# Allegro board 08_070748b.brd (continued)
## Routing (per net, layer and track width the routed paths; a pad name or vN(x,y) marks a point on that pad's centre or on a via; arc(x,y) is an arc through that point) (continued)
VOSNS0+: length 123.2
  LAYER_3 w0.254: TP16.1 v1(143.51,97.92)
  LAYER_4 w0.152: 95.76,82.8 95.73,82.77 91.78,82.77 v2(91.26,82.26)
  LAYER_4 w0.254: TP16.1 134.24,112.4 125.83,103.99 v1(123.19,101.35) 123.19,100.19 107.96,84.96 97.46,84.96 96.39,83.89 96.39,83.44 95.76,82.8
  LAYER_5 w0.254: v1(152.15,87.63) 152.15,87.63 152.15,92.07 150.62,93.6 130.94,93.6 v1(123.19,101.35)
  BOTTOM w0.254: R79.1 v1(143.51,97.92) ; R121.2 v1(152.15,87.63)
  BOTTOM w0.381: R61.2 TP16.1
VOSNS0-: length 196
  LAYER_4 w0.152: v2(91.26,83.26) 91.39,83.38 91.58,83.38 91.93,83.74 95.59,83.74 95.76,83.91
  LAYER_4 w0.203: v1(122.49,101.46) 122.47,101.46 122.47,101.46 ; 95.8,83.95 95.76,83.91
  LAYER_4 w0.254: v1(197.1,105.41) 197.1,105.54 197.49,105.92 TP17.1 183.77,113.92 168.91,113.92 164.59,109.6 154.81,109.6 149.35,115.06 142.37,115.06 140.21,112.9 133.91,112.9 122.47,101.46 ; v1(122.49,101.46) 122.49,100.14 107.82,85.47 97.32,85.47 95.8,83.95
  LAYER_5 w0.254: v1(152.15,86.11) 151.51,86.74 151.51,91.95 150.37,93.09 130.68,93.09 123.01,100.76 122.95,100.76 122.49,101.22 v1(122.49,101.46)
  BOTTOM w0.254: R80.1 v1(197.1,105.41) ; R122.2 v1(152.15,86.11)
  BOTTOM w0.381: R62.1 TP17.1
VOSNS1+: length 78.2
  LAYER_3 w0.254: v1(141.99,79.76) 143.51,81.28 TP18.1
  LAYER_4 w0.381: v1(143.51,94.74) TP18.1
  LAYER_5 w0.152: 95.54,84.74 89.06,84.74 89.04,84.71 88.72,84.71 v2(88.27,84.26)
  LAYER_5 w0.254: 95.54,84.74 95.91,84.74 98.81,87.63 TP18.1
  BOTTOM w0.254: R63.2 TP18.1 ; v1(141.99,79.76) 142.45,80.22 R96.1 ; R79.2 v1(143.51,94.74)
VOSNS1-: length 131.3
  LAYER_4 w0.152: v2(88.27,85.26) 87.78,84.77 87.78,83.06 88.54,82.29 88.54,82.22 88.83,81.94 88.9,81.94 89.06,81.77 95.76,81.77
  LAYER_4 w0.203: v1(197.1,102.11) 192.33,97.33
  LAYER_4 w0.254: 192.33,97.33 183.51,88.52 TP19.1 182.5,82.17 110.62,82.17 109.21,80.76 96.77,80.76 95.76,81.77
  BOTTOM w0.254: R64.1 TP19.1 R97.1 ; R80.2 v1(197.1,102.11)
VOSNS2+: length 76.3
  LAYER_3 w0.254: TP12.1 143.51,72.52 143.38,72.64 143.38,77.6 v1(141.99,78.99)
  LAYER_4 w0.254: TP12.1 v1(143.51,67.82)
  LAYER_5 w0.152: v2(88.27,77.26) 88.78,76.74 95.47,76.74 95.5,76.71 95.76,76.71
  LAYER_5 w0.254: 95.76,76.71 96.52,75.95 96.52,74.68 99.31,71.88 TP12.1
  BOTTOM w0.254: R96.2 142.45,78.53 v1(141.99,78.99) ; R17.2 146.2,71.09 145.41,71.88 TP12.1 ; v1(143.51,67.82) R108.1
VOSNS2-: length 130.4
  LAYER_4 w0.152: 95.76,76.87 95.63,76.74 89.06,76.74 89.03,76.71 88.72,76.71 v2(88.27,76.26)
  LAYER_4 w0.254: v1(197.1,57.53) 197.1,58.17 183.51,71.75 TP14.1 180.97,73.03 176.02,73.03 174.24,74.8 112.9,74.8 108.59,79.12 98.01,79.12 95.76,76.87
  BOTTOM w0.254: R20.1 TP14.1 R97.2 ; v1(197.1,57.53) R109.1
VOSNS3+: length 87.1
  LAYER_3 w0.254: v1(143.51,64.77) TP13.1
  LAYER_4 w0.152: 95.76,75.74 91.78,75.74 v2(91.26,76.26)
  LAYER_4 w0.203: 95.76,75.74 95.8,75.74
  LAYER_4 w0.254: TP13.1 133.6,46.99 106.54,74.06 97.49,74.06 95.8,75.74
  BOTTOM w0.254: R108.2 v1(143.51,64.77) ; R8.2 TP13.1
VOSNS3-: length 156.5
  LAYER_4 w0.152: v2(91.26,75.26) 91.45,75.26 91.61,75.09 91.62,75.09 91.94,74.77 95.76,74.77
  LAYER_4 w0.254: 95.76,74.77 95.91,74.77 97.09,73.6 106.23,73.6 133.35,46.48 140.21,46.48 143,43.69 144.91,43.69 150.5,38.1 163.45,38.1 170.94,45.59 182.37,45.59 TP15.1
  LAYER_6 w0.254: TP15.1 196.34,31.88 196.6,31.88 198.5,33.78 198.5,52.83 v1(197.1,54.23)
  BOTTOM w0.254: R109.2 v1(197.1,54.23) ; R9.1 TP15.1
VOUT0: length 152.2
  LAYER_4 w0.254: J3.1 127.51,147.17 107.95,127.61 107.95,91.44 107.57,91.06 v1(106.93,91.06)
  LAYER_5 w0.254: v1(150.24,112.4) 148.34,112.4 139.57,103.63 120.41,103.63 110.58,93.8 104.7,93.8 104.44,93.55 104.44,91.58 104.96,91.06 v1(105.03,91.06)
  BOTTOM w0.305: v1(105.03,91.06) 105.03,90.17 105.16,90.04 106.68,90.04 106.93,90.3 v1(106.93,91.06)
  BOTTOM w0.381: R61.1 v1(150.24,112.4)
  BOTTOM w0.508: J3.1 C71.1
  BOTTOM w1.27: 120.78,152.02 118.76,152.02 C84.2 C79.1 120.77,152.01 120.78,152.02 ; 120.78,152.02 J3.1 127.52,152.01 C75.1
  vias: v1(97.41,91.06) v1(98.42,91.06) v1(99.31,91.06) v1(101.22,91.06) v1(102.23,91.06) v1(103.12,91.06) v1(106.05,91.06) v1(121.92,116.59) v1(121.92,114.68) v1(123.83,116.59) v1(123.83,114.68) v1(125.73,116.59) v1(125.73,114.68) v1(127.63,116.59) v1(127.63,114.68) v1(128.52,118.75) v1(129.54,118.75) v1(129.54,116.59) v1(129.54,114.68) v1(130.43,118.75) v1(131.44,116.59) v1(131.44,114.68) v1(134.24,118.62) v1(135.25,118.62) v1(136.14,118.62) v1(139.32,118.62) v1(140.34,118.62) v1(140.97,107.19) v1(141.22,118.62) v1(141.61,107.19) v1(144.53,118.62) v1(144.53,106.3) v1(144.53,105.66) v1(145.54,118.62) v1(146.43,118.62) v1(146.69,107.19) v1(147.7,107.19) v1(148.72,107.19) v1(149.48,118.62) v1(150.5,118.62) v1(151.38,118.62) v1(151.76,107.19) v1(152.78,107.19) v1(153.67,107.19) v1(153.92,119) v1(154.94,119) v1(155.83,119) v1(156.72,107.19) v1(157.73,107.19) v1(158.75,107.19) v1(161.67,107.19) v1(162.69,107.19) v1(163.7,107.19) v1(166.37,122.17) v1(166.37,121.41) v1(166.37,120.52) v1(166.37,119.76) v2(93.26,90.26) v2(93.26,89.26) v2(93.26,88.26) v2(93.26,87.26) v2(93.26,86.26) v2(94.26,90.26) v2(94.26,89.26) v2(94.26,88.26) v2(94.26,87.26) v2(94.26,86.26) v2(95.26,90.26) v2(95.26,89.26) v2(95.26,88.26) v2(95.26,87.26) v2(95.26,86.26)
VOUT0_CFG: length 94.7
  LAYER_4 w0.152: 88.23,90.77 88.23,90.29
  LAYER_4 w0.203: 88.23,90.77 88.65,91.19 88.65,92.63 88.06,93.21 88.06,111.33 81.92,117.48 v1(81.92,118.24) ; 88.23,90.29 v2(88.27,90.26)
  LAYER_5 w0.203: v2(88.27,90.26) 88.27,90.81 87.89,91.19 v1(79.25,91.19)
  LAYER_6 w0.203: v1(79.25,91.19) 79.25,87.44 79.35,87.34 79.35,70.36 79.25,70.25 79.25,46.35 v1(84.07,41.53)
  BOTTOM w0.203: R55.1 v1(81.92,118.24) R46.2 ; R54.1 v1(84.07,41.53)
VOUT1: length 182.5
  TOP w0.381: CO12.2 98.42,83.69
  LAYER_5 w0.254: J4.1 194.44,89.66 191.52,86.74 191.52,85.72 186.31,80.52 181.17,80.52 180.59,81.09 110.11,81.09 108.38,82.81 107.07,82.81 v1(107.06,82.8) ; v1(155.45,87.63) 157.35,85.72 168.15,85.72 v1(169.04,86.61)
  LAYER_6 w0.254: v1(150.37,87.63) 147.45,84.71 109.35,84.71 108.59,83.95 106.93,83.95 106.17,83.19 v1(106.17,82.8)
  BOTTOM w0.203: CO37.2 168.91,86.49 v1(169.04,86.61)
  BOTTOM w0.254: v1(155.45,87.63) R121.1 ; R63.1 v1(150.37,87.63) ; v1(106.17,82.8) CO10.2 106.81,83.82 107.06,83.57 v1(107.06,82.8)
  BOTTOM w0.508: J4.1 C72.1
  BOTTOM w1.27: C80.1 J4.1 C76.1 C85.2
  vias: v1(97.54,83.06) v1(98.42,83.06) v1(99.31,83.06) v1(101.35,83.06) v1(102.23,83.06) v1(103.12,83.06) v1(105.28,83.06) v1(113.41,88.9) v1(114.3,88.9) v1(115.19,88.9) v1(118.49,88.9) v1(119.38,88.9) v1(120.27,88.9) v1(123.57,88.9) v1(124.46,88.9) v1(125.35,88.9) v1(128.27,101.35) v1(128.27,99.44) v1(128.65,88.9) v1(129.54,88.9) v1(130.18,101.35) v1(130.18,99.44) v1(130.43,88.9) v1(132.08,101.35) v1(132.08,99.44) v1(133.99,101.35) v1(133.99,99.44) v1(134.37,88.9) v1(135.25,88.9) v1(135.89,101.35) v1(135.89,99.44) v1(136.14,88.9) v1(137.8,101.35) v1(137.8,99.44) v1(141.1,99.57) v1(141.86,99.57) v1(144.53,100.46) v1(144.53,99.69) v1(146.05,83.19) v1(146.69,99.69) v1(146.94,83.19) v1(147.7,99.69) v1(147.83,83.19) v1(148.72,99.69) v1(151.13,83.19) v1(151.76,99.69) v1(152.02,83.19) v1(152.78,99.69) v1(152.91,83.19) v1(153.8,99.69) v1(155.83,83.19) v1(156.46,99.69) v1(156.84,83.19) v1(157.48,99.69) v1(157.86,83.19) v1(158.5,99.69) v1(161.04,83.19) v1(161.42,99.69) v1(161.93,83.19) v1(162.56,99.69) v1(162.81,83.19) v1(163.58,99.69) v1(165.99,83.19) v1(166.88,83.19) v1(167.77,83.19) v2(93.26,85.26) v2(93.26,84.26) v2(93.26,83.26) v2(93.26,82.26) v2(93.26,81.26) v2(94.26,85.26) v2(94.26,84.26) v2(94.26,83.26) v2(94.26,82.26) v2(94.26,81.26) v2(95.26,85.26) v2(95.26,84.26) v2(95.26,83.26) v2(95.26,82.26) v2(95.26,81.26)
VOUT1_CFG: length 102.1
  LAYER_4 w0.152: 87.75,90.81 87.75,89.77 v2(88.27,89.26)
  LAYER_4 w0.203: 87.75,90.81 87.75,91.95 87.5,92.2 87.5,92.66 87.66,92.82 87.66,110.85 v1(80.01,118.49)
  LAYER_5 w0.152: v2(88.27,89.26) 87.76,89.76 87.76,90.45 87.44,90.76
  LAYER_5 w0.203: 87.44,90.76 79.97,90.76 79.83,90.63 79.02,90.63 78.9,90.74 v1(78.17,90.74)
  LAYER_6 w0.203: v1(78.17,90.74) 78.17,87.95 78.94,87.17 78.94,70.52 78.49,70.07 78.49,46.23 83.19,41.53 v1(83.19,38.99)
  BOTTOM w0.203: R131.1 R54.2 v1(83.19,38.99) ; R47.2 v1(80.01,118.49) R56.1
VOUT2: length 165
  LAYER_5 w0.254: v1(107.06,76.2) 107.95,76.2 109.6,77.85 185.42,77.85 193.42,69.85 J5.1
  LAYER_6 w0.254: v1(106.17,76.2) 107.19,75.18 148.97,75.18 150.22,73.94 v1(150.22,71.09)
  BOTTOM w0.203: 203.67,69.85 C77.1 ; 188.69,69.86 C81.1
  BOTTOM w0.254: R17.1 v1(150.22,71.09)
  BOTTOM w0.381: v1(107.06,76.2) 107.06,75.82 106.43,75.18 CO20.2 v1(106.17,76.2)
  BOTTOM w0.508: C73.1 J5.1
  BOTTOM w1.27: 203.67,69.85 J5.1 188.72,69.85 188.71,69.86 C86.2
  vias: v1(97.54,76.2) v1(98.42,76.2) v1(99.31,76.2) v1(101.35,76.2) v1(102.23,76.2) v1(103.12,76.2) v1(105.28,76.2) v1(113.41,73.03) v1(114.3,73.03) v1(115.19,73.03) v1(118.49,73.03) v1(119.38,73.03) v1(120.27,73.03) v1(123.57,73.03) v1(124.46,73.03) v1(125.35,73.03) v1(128.27,69.6) v1(128.27,67.69) v1(128.65,73.03) v1(129.54,73.03) v1(130.18,69.6) v1(130.18,67.69) v1(130.43,73.03) v1(132.08,69.6) v1(132.08,67.69) v1(133.99,69.6) v1(133.99,67.69) v1(134.37,73.03) v1(135.25,73.03) v1(135.89,69.6) v1(135.89,67.69) v1(136.14,73.03) v1(137.8,69.6) v1(137.8,67.69) v1(141.1,59.94) v1(141.1,59.31) v1(141.1,58.67) v1(141.73,58.67) v1(146.05,76.71) v1(146.81,59.94) v1(146.94,76.71) v1(147.7,59.94) v1(147.83,76.71) v1(148.59,59.94) v1(151,76.71) v1(151.89,76.71) v1(151.89,59.94) v1(152.78,76.71) v1(152.78,59.94) v1(153.67,59.94) v1(156.08,76.71) v1(156.59,59.94) v1(156.97,76.71) v1(157.48,59.94) v1(157.86,76.71) v1(158.37,59.94) v1(160.91,76.71) v1(161.8,76.71) v1(161.8,59.94) v1(162.69,76.71) v1(162.69,59.94) v1(163.58,59.94) v1(165.99,76.71) v1(166.88,76.71) v1(167.77,76.71) v2(93.26,78.26) v2(93.26,77.26) v2(93.26,76.26) v2(93.26,75.26) v2(93.26,74.26) v2(94.26,78.26) v2(94.26,77.26) v2(94.26,76.26) v2(94.26,75.26) v2(94.26,74.26) v2(95.26,78.26) v2(95.26,77.26) v2(95.26,76.26) v2(95.26,75.26) v2(95.26,74.26)
VOUT2_CFG: length 34.6
  LAYER_4 w0.152: 87.63,68.71 87.78,68.86 87.78,69.46 88,69.67 88,69.71 88.27,69.97 v2(88.27,70.26)
  LAYER_4 w0.203: 87.63,68.71 87.22,68.3 87.22,62.25 87.25,62.22 87.25,43.05 v1(88.9,41.4)
  BOTTOM w0.203: R23.1 v1(88.9,41.4) R11.2 R140.1 R131.2
VOUT3: length 149.5
  TOP w0.381: CO28.2 v1(98.42,68.33)
  LAYER_4 w0.254: v1(106.97,68.36) 107.52,67.81 107.52,67.32 106.55,66.36 106.55,31.75 127.51,10.8 J6.1
  LAYER_5 w0.254: v1(150.11,46.99) 130.81,66.29 110.24,66.29 107.44,69.09 106.68,69.09 106.05,68.45 v1(106.05,68.33)
  BOTTOM w0.203: v1(106.97,68.36) 106.97,68.42 CO29.2 ; 129.54,39.5 v1(129.54,40.77) ; 106.05,69.28 v1(106.05,68.33)
  BOTTOM w0.254: R8.1 v1(150.11,46.99)
  BOTTOM w0.508: C74.1 J6.1
  BOTTOM w1.27: C78.1 134.71,7.49 J6.1 127.47,7.53 C82.1 C87.2
  vias: v1(97.54,68.33) v1(99.31,68.33) v1(101.35,68.33) v1(102.23,68.33) v1(103.12,68.33) v1(105.16,68.33) v1(121.92,46.1) v1(121.92,44.2) v1(123.83,46.1) v1(123.83,44.2) v1(125.73,46.1) v1(125.73,44.2) v1(127.63,46.1) v1(127.63,44.2) v1(128.65,40.77) v1(129.54,46.1) v1(129.54,44.2) v1(130.43,40.77) v1(131.44,46.1) v1(131.44,44.2) v1(134.37,40.77) v1(135.25,40.77) v1(136.14,40.77) v1(139.45,40.77) v1(140.34,40.77) v1(141.1,53.72) v1(141.1,53.09) v1(141.1,52.32) v1(141.22,40.77) v1(141.86,52.32) v1(144.53,40.77) v1(145.41,40.77) v1(146.3,40.77) v1(146.81,52.45) v1(147.7,52.45) v1(148.59,52.45) v1(149.48,40.77) v1(150.37,40.77) v1(151.26,40.77) v1(151.89,52.45) v1(152.78,52.45) v1(153.67,52.45) v1(154.05,40.51) v1(154.94,40.51) v1(155.83,40.51) v1(156.84,52.45) v1(157.73,52.45) v1(158.62,52.45) v1(161.54,52.45) v1(162.43,52.45) v1(163.32,52.45) v1(166.37,39.24) v1(166.37,38.61) v1(166.37,37.97) v1(166.37,37.34) v2(93.26,73.26) v2(93.26,72.26) v2(93.26,71.26) v2(93.26,70.26) v2(93.26,69.26) v2(94.26,73.26) v2(94.26,72.26) v2(94.26,71.26) v2(94.26,70.26) v2(94.26,69.26) v2(95.26,73.26) v2(95.26,72.26) v2(95.26,71.26) v2(95.26,70.26) v2(95.26,69.26)
VOUT3_CFG: length 60.8
  LAYER_4 w0.152: 88.21,68.71 88.27,68.76 v2(88.27,69.26)
  LAYER_4 w0.203: 88.21,68.71 87.63,68.13 87.63,62.42 88.27,61.78 88.27,46.1 90.81,43.56 v1(90.81,41.4)
  LAYER_6 w0.203: v2(88.27,69.26) 86.36,67.35 86.36,46.48 85.6,45.72 85.6,41.66 v1(85.72,41.53)
  BOTTOM w0.203: v1(85.72,41.53) 85.64,41.44 R140.2 ; R24.1 v1(90.81,41.4) R12.2
VTRIM0_CFG: length 34.8
  LAYER_6 w0.152: v2(89.26,87.26) 89.08,87.26 88.56,87.77 88.06,87.77 87.78,88.06 87.78,90.65 87.63,90.81
  LAYER_6 w0.203: v1(87.63,118.24) 87.63,118.02 87.79,117.86 87.79,93.01 87.82,92.98 87.83,92.99 88.29,92.99 88.62,92.66 88.62,92.2 88.29,91.87 87.93,91.87 87.63,91.57 87.63,90.81
  BOTTOM w0.203: R57.1 v1(87.63,118.24) R48.2
VTRIM1_CFG: length 42.9
  LAYER_4 w0.152: v2(89.26,88.26) 88.78,88.74 88.78,90.59 89,90.81
  LAYER_4 w0.203: v1(83.82,118.24) 83.82,116.45 88.47,111.8 88.47,93.38 89.05,92.8 89.05,90.86 89,90.81
  LAYER_5 w0.203: v1(83.82,118.24) 82.93,119.13 78.99,119.13 v1(78.11,118.24)
  BOTTOM w0.203: R125.2 R137.1 v1(78.11,118.24) ; R49.2 v1(83.82,118.24) R58.1
VTRIM2_CFG: length 97.1
  LAYER_4 w0.152: v2(90.26,69.26) 90.26,68.71
  LAYER_4 w0.203: 90.26,68.71 90.26,63.09 90.42,62.93 90.42,61.46 90.26,61.3 90.26,49.44 96.4,43.31 98.04,43.31 98.98,42.37 98.98,41.04 98.66,40.72 97.08,40.72 v1(96.52,41.27)
  LAYER_5 w0.152: 80.77,69.77 89.75,69.77 v2(90.26,69.26)
  LAYER_5 w0.203: 80.77,69.77 79.32,69.77 v1(78.36,70.73)
  LAYER_6 w0.203: v1(78.36,70.73) 78.36,79.35 78.54,79.52 78.54,79.99 78.51,80.01 78.51,82.25 77.22,83.54 v1(77.22,115.74)
  BOTTOM w0.203: R25.1 v1(96.52,41.27) R13.2 ; R145.1 v1(77.22,115.74) R137.2
VTRIM3_CFG: length 93.5
  LAYER_4 w0.152: v2(89.26,69.26) 89.26,68.71
  LAYER_4 w0.203: 89.26,68.71 89.26,62.94 89.61,62.59 89.61,61.79 89.26,61.45 89.26,49.29 94.62,43.94 v1(94.61,41.4)
  LAYER_5 w0.203: v2(89.26,69.26) 88.28,68.28 v1(76.07,68.28)
  LAYER_6 w0.203: v1(74.72,115.74) 74.72,83.45 75.97,82.19 75.97,79.91 75.95,79.89 75.95,79.53 75.97,79.5 75.97,68.38 v1(76.07,68.28)
  BOTTOM w0.203: R14.2 v1(94.61,41.4) R26.1

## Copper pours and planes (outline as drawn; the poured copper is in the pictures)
AGND on LAYER_2: 89.92,85.6 89.92,84.84 91.57,84.84 91.57,85.6
AGND on LAYER_2: 89.92,74.68 89.92,73.91 91.57,73.91 91.57,74.68
GND_POWER on TOP: 1.27,158.75 237.49,158.75 237.49,1.27 1.27,1.27
GND_POWER on BOTTOM: 117.35,6.48 117.35,2.79 125.73,2.79 125.73,6.48
GND_POWER on BOTTOM: 117.98,156.59 117.98,153.03 126.11,153.03 126.11,156.59
GND_POWER on BOTTOM: 129.16,156.59 129.16,153.03 135.25,153.03 135.25,156.59
GND_POWER on BOTTOM: 129.16,6.48 129.16,2.79 135.38,2.79 135.38,6.48
GND_POWER on BOTTOM: 186.06,70.61 186.06,64.9 194.94,64.9 194.94,70.61
GND_POWER on BOTTOM: 197.87,68.96 197.87,64.9 204.34,64.9 204.34,68.96
GND_POWER on BOTTOM: 197.99,88.77 197.99,85.09 204.47,85.09 204.47,88.77
GND_POWER on BOTTOM: 1.27,158.75 1.27,1.27 237.49,1.27 237.49,158.75 ; 16 cut-outs
GND_POWER on BOTTOM: 185.93,88.77 185.93,85.09 194.69,85.09 194.69,88.77
GND_POWER on LAYER_2, LAYER_3, LAYER_7: 1.27,158.75 1.27,1.27 237.49,1.27 237.49,158.75
GND_POWER on LAYER_4: 1.27,158.75 237.49,158.75 237.49,1.27 1.27,1.27 ; 15 cut-outs
GND_POWER on LAYER_5: 1.27,158.75 237.49,158.75 237.49,1.27 1.27,1.27 ; 11 cut-outs
GND_POWER on LAYER_6: 1.27,158.75 237.49,158.75 237.49,1.27 1.27,1.27 ; 2 cut-outs
VIN on BOTTOM (solid shape): 41.15,101.6 39.24,101.6 39.24,105.79 41.15,105.79
VIN on BOTTOM (solid shape): 41.15,53.34 39.24,53.34 39.24,57.53 41.15,57.53
VIN on TOP: 1.27,109.98 8.89,109.98 8.89,108.33 64.52,108.33 64.52,51.31 22.1,51.31 22.1,80.77 1.27,80.77 ; 2 cut-outs
VIN on BOTTOM: 8.89,109.98 8.89,108.33 64.52,108.33 64.52,51.31 22.1,51.31 22.1,80.77 1.27,80.77 1.27,109.98 ; 2 cut-outs
VIN01 on TOP, BOTTOM: 64.77,108.33 86.61,108.33 86.61,81.03 84.84,81.03 84.84,98.81 64.77,98.81
VIN23 on TOP, BOTTOM: 64.77,60.71 84.84,60.71 84.84,78.49 86.61,78.49 86.61,51.31 64.77,51.31
Net_2 on LAYER_2 (solid shape): 92.71,84.84 91.19,84.84 91.19,85.6 92.71,85.6
Net_2 on LAYER_2 (solid shape): 92.71,73.91 91.19,73.91 91.19,74.68 92.71,74.68
UNNAMED_2_ADLTM4683_I1_SW01 on TOP: 80.9,86.26 78.49,86.26 78.49,88.39 80.9,88.39 80.9,88.65 82.57,88.65 82.57,85.85 80.9,85.85
UNNAMED_2_ADLTM4683_I1_SW11 on TOP: 80.87,82.2 78.49,82.2 78.49,84.33 80.9,84.33 80.9,84.71 82.57,84.71 82.57,81.79 80.87,81.79
UNNAMED_2_ADLTM4683_I1_SW21 on TOP: 80.87,75.08 78.49,75.08 78.49,77.22 80.9,77.22 80.9,77.6 82.57,77.6 82.57,74.93 80.87,74.93
UNNAMED_2_ADLTM4683_I1_SW31 on TOP: 80.87,71.27 78.49,71.27 78.49,73.41 80.9,73.41 80.9,73.66 82.57,73.66 82.57,70.87 80.87,70.87
UNNAMED_4_CAP_I295_N2 on BOTTOM: 157.86,131.57 176.4,131.57 176.4,98.81 169.16,98.81 169.16,123.83 157.86,123.83
UNNAMED_4_CAP_I345_N2 on BOTTOM: 176.4,60.71 176.4,27.69 157.86,27.69 157.86,35.69 169.16,35.69 169.16,60.71
UNNAMED_4_CNBNC5P_I301_CNTR on BOTTOM: 162.56,146.69 173.23,146.69 173.23,132.84 169.67,132.84 169.67,136.91 164.97,136.91 164.97,132.84 162.56,132.84
UNNAMED_4_CNBNC5P_I354_CNTR on BOTTOM: 157.86,26.8 161.16,26.8 161.16,22.99 164.72,22.99 164.72,26.54 168.53,26.54 168.53,13.21 157.86,13.21
VOUT0 on TOP: 124.82,123.57 168.91,123.57 168.91,103.38 126.2,103.38 108.77,85.85 92.96,85.85 92.96,91.31 107.31,91.31 107.7,91.69 107.7,98.04 116.05,110.49 119.17,115.09
VOUT0 on BOTTOM: 168.91,103.38 126.2,103.38 108.77,85.85 92.96,85.85 92.96,91.31 103.39,91.31 103.4,91.32 107.31,91.31 107.7,91.69 107.7,98.04 124.82,123.57 168.91,123.57 ; 1 cut-out
VOUT1 on TOP: 126.44,103.12 168.91,103.12 168.91,81.79 144.91,81.79 144.91,82.68 96.01,82.68 96.01,80.9 92.96,80.9 92.96,85.6 108.82,85.6
VOUT1 on BOTTOM: 126.44,103.12 168.91,103.12 168.91,81.79 144.91,81.79 144.91,82.68 96.01,82.68 96.01,80.9 92.96,80.9 92.96,85.6 108.82,85.6 ; 2 cut-outs
VOUT2 on TOP: 92.96,78.61 96.01,78.61 96.01,76.71 144.91,76.71 144.91,77.72 168.91,77.72 168.91,56.39 127.66,56.39 110.04,73.91 92.96,73.91
VOUT2 on BOTTOM: 96.01,76.71 144.91,76.71 144.91,77.72 168.91,77.72 168.91,56.39 127.66,56.39 110.29,73.66 92.96,73.66 92.96,78.61 96.01,78.61 ; 1 cut-out
VOUT3 on TOP: 92.96,73.66 109.95,73.66 127.38,56.13 168.91,56.13 168.91,35.92 125.32,35.92 107.7,61.75 107.69,68.07 92.96,68.07
VOUT3 on BOTTOM: 92.96,73.66 109.95,73.66 127.38,56.13 168.91,56.13 168.91,35.94 125.31,35.92 107.7,61.72 107.7,68.07 92.96,68.07 ; 2 cut-outs

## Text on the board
Ref Des/Silkscreen Bottom: 08-070748B | TSNS0 | TSNS1 | TSNS2 | TSNS3 | 2 | 1
User.Comments: 4 | A1Z | A2Z | VARIANTS | 4 PHASE 4 OUTPUT | 4 PHASE 1 OUTPUT | CIRCUIT CONFIGUATION | 125A | 31.25A PER CHANNEL | MAX OUTPUT CURRENT | PLEASE SEE BILL OF MATERILL TO MARK EACH VERSION CORRECTLY | WITH BLACK PERMANENT MARKER INSIDE SILKSCREEN BLOCK PROVIDE | 4.    THERE ARE 2 ASSEMBLY VARIANTS 01-070748B-01, 01-070748B-02. | *ASSEMBLY OPTION TABLE | Delete if not required. | Alternative Logo Size.
Ref Des/Silkscreen Top: ON | GND | VIN | RUN3 | RUN2 | RUN1 | RUN0 | OFF | 4.5V-14V | RUNP | WP_23 | WP_01 | VBIAS | SGND | INTVCC_01 | INTVCC_23 | VDD33_01 | VDD33_23 | VDD25_01 | PGOOD2 | PGOOD0 | PGOOD1 | PGOOD3 | VDD25_23 | VOUT0 | VOUT3 | VOUT0+ | VOUT1+ | VOUT2+ | VOUT3+ | IOSTEP_CLK01 | IOSTEP_CLK23 | VOUT1 | VOUT2 | 0.4V/31.25A | IOSTEP_23 | IOSTEP_01 | VOUT1- | VOUT2- | ALERTB_23 | ALERTB_01 | VOUT3- | VOUT0- | SHARE_CLK | FAULT0B | FAULT1B | FAULT2B | FAULT3B | ALERTB | AUXP | SYNC | 3V3 | SDA | SCL | SWR1 | SWR3 | SWR2 | SWR0 | TO DC2086A | TO DC1613A | A1Z | A2Z | VARIANTS | 4 PHASE 4 OUTPUT | 4 PHASE 1 OUTPUT | CKT.CONFIGURATION | 125A | MAX IOUT | 31.25A/CHANNEL | 01-070748- | 125A PSM uMODULE REGULATOR | LOW VOUT QUAD 31.25A OR SINGLE | EVAL-LTM4683-A  Z | LTM4683
PAGE_OUTLINE: B
User.15: .0028" | .0059" | .0035" | PRIMARY SILKSCREEN | PRIMARY SOLDER MASK | PRIMARY SIDE        (LAYER 1) | GROUND              (LAYER 2) | SGROUND / INTERNAL1 (LAYER 3) | GROUND / INTERNAL2  (LAYER 4) | GROUND / INTERNAL3  (LAYER 5) | GROUND / INTERNAL4  (LAYER 6) | GROUND              (LAYER 7) | SECONDARY SIDE      (LAYER 8) | SECONDARY SOLDER MASK | SECONDARY SILKSCREEN | CLADDING; | IC_U1; | VIA HOLES; | PER IPC-4552 LATEST REVISION | EXTERNAL LAYERS 1 OZ. COPPER, OVERPLATE TO 3 OZ. | INTERNAL LAYERS 2 OZ. COPPER. | DESIGN HAS SOLDER MASK DEFINED PADS ON U1. | U1 SOLDERMASK IS 20 MIL AND PAD SIZE IS 24 MIL. | DO NOT CHANGE PAD SIZE OR SOLDER MASK SIZE. | ENIG (Electroless Nickel/Immersion Gold) | PLUG ALL VIA'S WITH CONDUCTIVE COPPER AND PLATE OVER. | PLANARIZE FINAL SURFACE. | NOMINAL | FINISHED | THICKNESS | 0.062" +/-10% | 8 LAYER STACKUP
User.17: 08-      -07 | LAYER 2
User.18: LAYER 3 | 08-      -08
User.19: 08-      -09 | LAYER 4
User.20: 08-      -10 | LAYER 5
User.23: 08-      -11 | LAYER 6
User.24: 08-      -12 | LAYER 7
User.45: FIGURE | SIZE | 8.0 | 10.0 | 35.0 | 40.0 | 50.0 | 60.0 | 100.0 | 200.0 | 187.0 | PLATED | NON-PLATED | FINISHED HOLES IN MILS | ALL UNITS ARE IN MILS | QTY | 301 | 900 | 42 | 35 | 6 | 24 | 47 | 10 | 4 | TOLERANCE/NOTES
